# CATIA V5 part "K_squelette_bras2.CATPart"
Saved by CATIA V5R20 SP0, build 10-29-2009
Part number: squelette_bras2
Publications: "Droite.1", "axe-pivot23", "Point_centre_liaison_pivot12", "Point_centre_liaison_pivot23", "Plan.1", "axe_pivot12", "Point_centre_liaison_pivot121", "Plan.2", "Plan.31", "Plan.4", "Point.5", "Point.4", "Plan.5"
Bounding box of the stored display mesh (mm): x 0 to 100, y 0 to 0, z 130 to 170
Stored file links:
  G:\Khaled_CFAO_2011\SIL\SIL_GR2\pfradet\pfradet\Khaled\CAD_ThinkMOTION\K_squelette_bras2.CATPart
  G:\Khaled_CFAO_2011\SIL\SIL_GR2\pfradet\pfradet\Khaled\CAD_ThinkMOTION\K_squelette.CATProduct
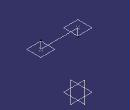
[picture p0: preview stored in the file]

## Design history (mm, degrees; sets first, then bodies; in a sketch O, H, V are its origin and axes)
Set1
  Point1 "Point_centre_liaison_pivot12": linked copy from another document
  Point2 "Point_centre_liaison_pivot23": linked copy from another document
  Plane1: linked copy from another document
  Plane2: linked copy from another document
  Point3 "Point_centre_liaison_pivot12": linked copy from another document
  Plane3: linked copy from another document
Set2
  Line1: type PtPt, FirstPoint Point1, SecondPoint Point2
  Line2 "axe-pivot23": type Normal, RefPoint Point2, RefSkin Plane1, Start 0, End 20
  Line3 "axe_pivot12": type Normal, RefPoint Point3, RefSkin Plane2, Start 0, End 20
  Plane4: type Offset, RefPlane Plane2, Offset 0
  Plane5: type Offset, RefPlane Plane3, Offset 0
  Point4: (0, 0, 0), relative to Point1
  Point5: (0, 0, 0), relative to Point2
Body1 (main body)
